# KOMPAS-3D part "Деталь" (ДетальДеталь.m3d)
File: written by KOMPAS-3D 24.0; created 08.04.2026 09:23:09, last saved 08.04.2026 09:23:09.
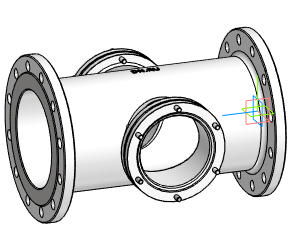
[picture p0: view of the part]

Document properties: Автор: Main; Полное имя файла: D:\DN.ru Аутсерс\Стекло смотровое DN.ru\Исходники\Стекло смотровое DN.ru SG2-34G-F тип В ГОСТ 21836-2021 Ду200 Ру16, углеродистая сталь, фланцевое\ДетальДеталь.m3d

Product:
- Body: Твердое тело1  | qty 1
- Part/product: Деталь
    additional columns: Типовые

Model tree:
1. Твердое тело1  (labels: Твердое тело1)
